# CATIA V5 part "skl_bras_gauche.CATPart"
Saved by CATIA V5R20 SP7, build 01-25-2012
Part number: skl_bras_gauche
Publications: "Axe_pivot_bras_gauche_bâti", "Axe_pivot_bras_gauche_patin_gauche", "Axe_pivot_bras_gauche_biellette_gauche", "Plan.1"
Bounding box of the stored display mesh (mm): x -524.226 to 0, y -390 to 700, z 0 to 20
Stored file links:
  U:\IAO\thinkmotion catia2\skl_bras_gauche.CATPart
  U:\IAO\thinkmotion catia2\skl_862_adubourgno.CATProduct
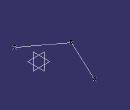
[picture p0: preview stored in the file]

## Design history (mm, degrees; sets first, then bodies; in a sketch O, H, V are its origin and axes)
Set1
  Point1 "I": linked copy from another document
  Point2 "E": linked copy from another document
  Point3 "C": linked copy from another document
  Plane1: linked copy from another document
Set2
  Line1: type PtPt, FirstPoint Point1, SecondPoint Point2
  Line2: type PtPt, FirstPoint Point1, SecondPoint Point3
  Line3 "Axe_pivot_bras_gauche_biellette_gauche": type Normal, RefPoint Point2, RefSkin Plane1, Start 0, End 20
  Line4 "Axe_pivot_bras_gauche_patin_gauche": type Normal, RefPoint Point1, RefSkin Plane1, Start 0, End 20
  Line5 "Axe_pivot_bras_gauche_bâti": type Normal, RefPoint Point3, RefSkin Plane1, Start 0, End 20
Body1 (main body)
